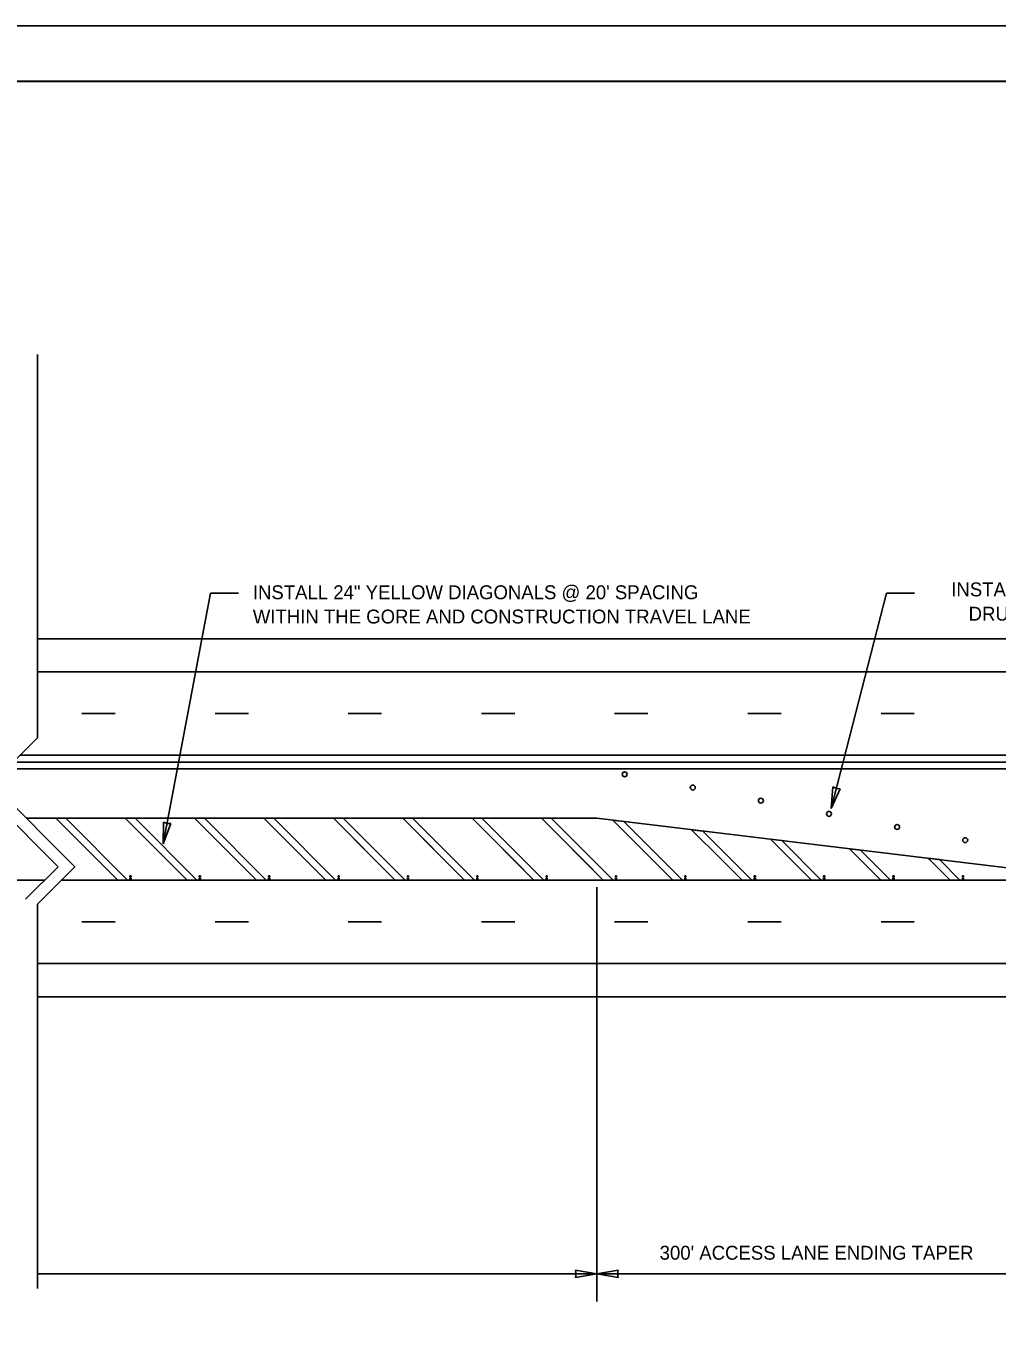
# Model space of a CAD drawing. Extents: x -2433 to -1135, y -5611 to -4633.
# Drawn here: x -1803.5 to -1523.6, y -5006.7 to -4632.8 of the extents above; entities that cross this region are included whole.
import ezdxf

# ---------------------------------------------------------------- set-up
doc = ezdxf.new("R2010")
doc.units = 0
for name, color, linetype in [('Level 42', 7, 'Continuous'), ('Level 45', 7, 'Continuous'), ('Level 46', 7, 'Continuous'), ('Level 48', 7, 'Continuous'), ('Level 49', 7, 'Continuous'), ('Level 50', 7, 'Continuous'), ('TR_WZ_TC_Edge Lines', 7, 'Continuous')]:
    doc.layers.add(name, color=color, linetype=linetype)

msp = doc.modelspace()

# ---------------------------------------------------------------- linework, layer by layer
at = {"layer": 'Level 42'}
msp.add_line((-1170.57, -4648.81), (-2364.77, -4648.78), dxfattribs=at)
msp.add_lwpolyline([(-2364.77, -4648.78), (-1304.73, -4648.78), (-1304.73, -5430.02), (-2364.77, -5430.02)], close=True, dxfattribs=at)
at = {"layer": 'Level 45'}
for p, q in [((-1805.25, -4843.04), (-1332.46, -4843.04)), ((-2323.46, -4879.04), (-1798.16, -4879.04)), ((-1793.36, -4879.04), (-1332.46, -4879.04)), ((-1773.56, -4878.08), (-1773.56, -4877.76)), ((-1773.56, -4877.76), (-1773.24, -4877.76)), ((-1773.24, -4878.08), (-1773.56, -4878.08)), ((-1773.56, -4878.72), (-1773.56, -4878.4)), ((-1773.56, -4878.4), (-1773.24, -4878.4)), ((-1773.24, -4878.72), (-1773.56, -4878.72)), ((-1773.24, -4877.76), (-1773.24, -4878.08)), ((-1773.24, -4878.4), (-1773.24, -4878.72)), ((-1753.56, -4878.08), (-1753.56, -4877.76)), ((-1753.56, -4877.76), (-1753.24, -4877.76)), ((-1753.24, -4878.08), (-1753.56, -4878.08)), ((-1753.56, -4878.72), (-1753.56, -4878.4)), ((-1753.56, -4878.4), (-1753.24, -4878.4)), ((-1753.24, -4878.72), (-1753.56, -4878.72)), ((-1753.24, -4877.76), (-1753.24, -4878.08)), ((-1753.24, -4878.4), (-1753.24, -4878.72)), ((-1733.56, -4878.08), (-1733.56, -4877.76)), ((-1733.56, -4877.76), (-1733.24, -4877.76)), ((-1733.24, -4878.08), (-1733.56, -4878.08)), ((-1733.56, -4878.72), (-1733.56, -4878.4)), ((-1733.56, -4878.4), (-1733.24, -4878.4)), ((-1733.24, -4878.72), (-1733.56, -4878.72)), ((-1733.24, -4877.76), (-1733.24, -4878.08)), ((-1733.24, -4878.4), (-1733.24, -4878.72)), ((-1713.56, -4878.08), (-1713.56, -4877.76)), ((-1713.56, -4877.76), (-1713.24, -4877.76)), ((-1713.24, -4878.08), (-1713.56, -4878.08)), ((-1713.56, -4878.72), (-1713.56, -4878.4)), ((-1713.56, -4878.4), (-1713.24, -4878.4)), ((-1713.24, -4878.72), (-1713.56, -4878.72)), ((-1713.24, -4877.76), (-1713.24, -4878.08)), ((-1713.24, -4878.4), (-1713.24, -4878.72)), ((-1693.56, -4878.08), (-1693.56, -4877.76)), ((-1693.56, -4877.76), (-1693.24, -4877.76)), ((-1693.24, -4878.08), (-1693.56, -4878.08)), ((-1693.56, -4878.72), (-1693.56, -4878.4)), ((-1693.56, -4878.4), (-1693.24, -4878.4)), ((-1693.24, -4878.72), (-1693.56, -4878.72)), ((-1693.24, -4877.76), (-1693.24, -4878.08)), ((-1693.24, -4878.4), (-1693.24, -4878.72)), ((-1673.56, -4878.08), (-1673.56, -4877.76)), ((-1673.56, -4877.76), (-1673.24, -4877.76)), ((-1673.24, -4878.08), (-1673.56, -4878.08)), ((-1673.56, -4878.72), (-1673.56, -4878.4)), ((-1673.56, -4878.4), (-1673.24, -4878.4)), ((-1673.24, -4878.72), (-1673.56, -4878.72)), ((-1673.24, -4877.76), (-1673.24, -4878.08)), ((-1673.24, -4878.4), (-1673.24, -4878.72)), ((-1653.56, -4878.08), (-1653.56, -4877.76)), ((-1653.56, -4877.76), (-1653.24, -4877.76)), ((-1653.24, -4878.08), (-1653.56, -4878.08)), ((-1653.56, -4878.72), (-1653.56, -4878.4)), ((-1653.56, -4878.4), (-1653.24, -4878.4)), ((-1653.24, -4878.72), (-1653.56, -4878.72)), ((-1653.24, -4877.76), (-1653.24, -4878.08)), ((-1653.24, -4878.4), (-1653.24, -4878.72)), ((-1633.56, -4878.08), (-1633.56, -4877.76)), ((-1633.56, -4877.76), (-1633.24, -4877.76)), ((-1633.24, -4878.08), (-1633.56, -4878.08)), ((-1633.56, -4878.72), (-1633.56, -4878.4)), ((-1633.56, -4878.4), (-1633.24, -4878.4)), ((-1633.24, -4878.72), (-1633.56, -4878.72)), ((-1633.24, -4877.76), (-1633.24, -4878.08)), ((-1633.24, -4878.4), (-1633.24, -4878.72)), ((-1613.56, -4878.08), (-1613.56, -4877.76)), ((-1613.56, -4877.76), (-1613.24, -4877.76)), ((-1613.24, -4878.08), (-1613.56, -4878.08)), ((-1613.56, -4878.72), (-1613.56, -4878.4)), ((-1613.56, -4878.4), (-1613.24, -4878.4)), ((-1613.24, -4878.72), (-1613.56, -4878.72)), ((-1613.24, -4877.76), (-1613.24, -4878.08)), ((-1613.24, -4878.4), (-1613.24, -4878.72)), ((-1593.56, -4878.08), (-1593.56, -4877.76)), ((-1593.56, -4877.76), (-1593.24, -4877.76)), ((-1593.24, -4878.08), (-1593.56, -4878.08)), ((-1593.56, -4878.72), (-1593.56, -4878.4)), ((-1593.56, -4878.4), (-1593.24, -4878.4)), ((-1593.24, -4878.72), (-1593.56, -4878.72)), ((-1593.24, -4877.76), (-1593.24, -4878.08)), ((-1593.24, -4878.4), (-1593.24, -4878.72)), ((-1573.56, -4878.08), (-1573.56, -4877.76)), ((-1573.56, -4877.76), (-1573.24, -4877.76)), ((-1573.24, -4878.08), (-1573.56, -4878.08)), ((-1573.56, -4878.72), (-1573.56, -4878.4)), ((-1573.56, -4878.4), (-1573.24, -4878.4)), ((-1573.24, -4878.72), (-1573.56, -4878.72)), ((-1573.24, -4877.76), (-1573.24, -4878.08)), ((-1573.24, -4878.4), (-1573.24, -4878.72)), ((-1553.56, -4878.08), (-1553.56, -4877.76)), ((-1553.56, -4877.76), (-1553.24, -4877.76)), ((-1553.24, -4878.08), (-1553.56, -4878.08)), ((-1553.56, -4878.72), (-1553.56, -4878.4)), ((-1553.56, -4878.4), (-1553.24, -4878.4)), ((-1553.24, -4878.72), (-1553.56, -4878.72)), ((-1553.24, -4877.76), (-1553.24, -4878.08)), ((-1553.24, -4878.4), (-1553.24, -4878.72)), ((-1533.56, -4878.08), (-1533.56, -4877.76)), ((-1533.56, -4877.76), (-1533.24, -4877.76)), ((-1533.24, -4878.08), (-1533.56, -4878.08)), ((-1533.56, -4878.72), (-1533.56, -4878.4)), ((-1533.56, -4878.4), (-1533.24, -4878.4)), ((-1533.24, -4878.72), (-1533.56, -4878.72)), ((-1533.24, -4877.76), (-1533.24, -4878.08)), ((-1533.24, -4878.4), (-1533.24, -4878.72))]:
    msp.add_line(p, q, dxfattribs=at)
at = {"layer": 'Level 46'}
for p, q in [((-1750.28, -4796.31), (-1763.96, -4868.57)), ((-1742.28, -4796.31), (-1750.28, -4796.31)), ((-1555.4, -4796.31), (-1571.36, -4858.37)), ((-1547.4, -4796.31), (-1555.4, -4796.31)), ((-1800.24, -4809.44), (-1332.46, -4809.44)), ((-1800.24, -4819.04), (-1332.46, -4819.04)), ((-1787.41, -4831.04), (-1777.81, -4831.04)), ((-1749.01, -4831.04), (-1739.41, -4831.04)), ((-1710.61, -4831.04), (-1701.01, -4831.04)), ((-1672.21, -4831.04), (-1662.61, -4831.04)), ((-1633.81, -4831.04), (-1624.21, -4831.04)), ((-1595.41, -4831.04), (-1585.81, -4831.04)), ((-1557.01, -4831.04), (-1547.41, -4831.04)), ((-1638.94, -4881.06), (-1638.94, -5000.52)), ((-1787.41, -4891.04), (-1777.81, -4891.04)), ((-1749.01, -4891.04), (-1739.41, -4891.04)), ((-1710.61, -4891.04), (-1701.01, -4891.04)), ((-1672.21, -4891.04), (-1662.61, -4891.04)), ((-1633.81, -4891.04), (-1624.21, -4891.04)), ((-1595.41, -4891.04), (-1585.81, -4891.04)), ((-1557.01, -4891.04), (-1547.41, -4891.04)), ((-1800.24, -4903.04), (-1332.46, -4903.04)), ((-1800.24, -4912.64), (-1332.46, -4912.64)), ((-1800.24, -4992.52), (-1491.33, -4992.52))]:
    msp.add_line(p, q, dxfattribs=at)
at = {"layer": 'Level 48'}
for p, q in [((-1807.25, -4845.04), (-1493.44, -4845.04)), ((-1494.3, -4846.96), (-1809.17, -4846.96))]:
    msp.add_line(p, q, dxfattribs=at)
at = {"layer": 'Level 49'}
for p, q in [((-1571.36, -4858.37), (-1570.88, -4852.15)), ((-1568.78, -4852.69), (-1571.36, -4858.37)), ((-1570.88, -4852.15), (-1569.88, -4852.6)), ((-1569.88, -4852.6), (-1568.78, -4852.69)), ((-1763.96, -4868.57), (-1763.88, -4862.33)), ((-1761.75, -4862.73), (-1763.96, -4868.57)), ((-1763.88, -4862.33), (-1762.85, -4862.72)), ((-1762.85, -4862.72), (-1761.75, -4862.73)), ((-1638.94, -4992.52), (-1645.09, -4991.43)), ((-1645.09, -4991.43), (-1644.9, -4992.52)), ((-1632.8, -4991.43), (-1638.94, -4992.52)), ((-1632.99, -4992.52), (-1632.8, -4991.43)), ((-1644.9, -4992.52), (-1645.09, -4993.6)), ((-1645.09, -4993.6), (-1638.94, -4992.52)), ((-1638.94, -4992.52), (-1632.8, -4993.6)), ((-1632.8, -4993.6), (-1632.99, -4992.52))]:
    msp.add_line(p, q, dxfattribs=at)
at = {"layer": 'Level 50'}
for p, q in [((-1800.24, -4838.04), (-1800.24, -4727.54)), ((-1813.42, -4851.21), (-1800.24, -4838.04)), ((-1794.28, -4875.16), (-1818.23, -4851.21)), ((-1789.47, -4875.16), (-1813.42, -4851.21)), ((-1803.64, -4884.52), (-1794.28, -4875.16)), ((-1800.24, -4885.93), (-1789.47, -4875.16)), ((-1800.24, -4885.93), (-1800.24, -4996.72))]:
    msp.add_line(p, q, dxfattribs=at)
msp.add_lwpolyline([(-2432.94, -4632.82), (-1157.59, -4632.82), (-1157.59, -5447.91), (-2432.94, -5447.91)], close=True, dxfattribs=at)
for centre in [(-1630.92, -4848.54), (-1611.28, -4852.34), (-1591.65, -4856.13), (-1572.01, -4859.93), (-1552.37, -4863.72), (-1532.74, -4867.52)]:
    msp.add_circle(centre, 0.72, dxfattribs=at)
at = {"layer": 'TR_WZ_TC_Edge Lines'}
for p, q in [((-1803.43, -4861.2), (-1638.94, -4861.2)), ((-1777.07, -4879.04), (-1794.91, -4861.2)), ((-1792.08, -4861.2), (-1794.91, -4861.2)), ((-1774.24, -4879.04), (-1792.08, -4861.2)), ((-1774.24, -4879.04), (-1792.08, -4861.2)), ((-1757.07, -4879.04), (-1774.91, -4861.2)), ((-1772.08, -4861.2), (-1774.91, -4861.2)), ((-1754.24, -4879.04), (-1772.08, -4861.2)), ((-1754.24, -4879.04), (-1772.08, -4861.2)), ((-1737.07, -4879.04), (-1754.91, -4861.2)), ((-1752.08, -4861.2), (-1754.91, -4861.2)), ((-1734.24, -4879.04), (-1752.08, -4861.2)), ((-1734.24, -4879.04), (-1752.08, -4861.2)), ((-1717.07, -4879.04), (-1734.91, -4861.2)), ((-1732.08, -4861.2), (-1734.91, -4861.2)), ((-1714.24, -4879.04), (-1732.08, -4861.2)), ((-1714.24, -4879.04), (-1732.08, -4861.2)), ((-1697.07, -4879.04), (-1714.91, -4861.2)), ((-1712.08, -4861.2), (-1714.91, -4861.2)), ((-1694.24, -4879.04), (-1712.08, -4861.2)), ((-1694.24, -4879.04), (-1712.08, -4861.2)), ((-1677.07, -4879.04), (-1694.91, -4861.2)), ((-1692.08, -4861.2), (-1694.91, -4861.2)), ((-1674.24, -4879.04), (-1692.08, -4861.2)), ((-1674.24, -4879.04), (-1692.08, -4861.2)), ((-1657.07, -4879.04), (-1674.91, -4861.2)), ((-1672.08, -4861.2), (-1674.91, -4861.2)), ((-1654.24, -4879.04), (-1672.08, -4861.2)), ((-1654.24, -4879.04), (-1672.08, -4861.2)), ((-1637.07, -4879.04), (-1654.91, -4861.2)), ((-1652.08, -4861.2), (-1654.91, -4861.2)), ((-1634.24, -4879.04), (-1652.08, -4861.2)), ((-1634.24, -4879.04), (-1652.08, -4861.2)), ((-1638.94, -4861.2), (-1491.33, -4879.04)), ((-1631.14, -4862.15), (-1634.35, -4861.76)), ((-1614.24, -4879.04), (-1631.14, -4862.15)), ((-1608.39, -4864.89), (-1611.61, -4864.51)), ((-1594.24, -4879.04), (-1608.39, -4864.89)), ((-1585.64, -4867.64), (-1588.86, -4867.26)), ((-1574.24, -4879.04), (-1585.64, -4867.64)), ((-1562.89, -4870.39), (-1566.11, -4870)), ((-1554.24, -4879.04), (-1562.89, -4870.39)), ((-1540.14, -4873.14), (-1543.36, -4872.75)), ((-1534.24, -4879.04), (-1540.14, -4873.14)), ((-1777.07, -4879.04), (-1774.24, -4879.04)), ((-1757.07, -4879.04), (-1754.24, -4879.04)), ((-1737.07, -4879.04), (-1734.24, -4879.04)), ((-1717.07, -4879.04), (-1714.24, -4879.04)), ((-1697.07, -4879.04), (-1694.24, -4879.04)), ((-1677.07, -4879.04), (-1674.24, -4879.04)), ((-1657.07, -4879.04), (-1654.24, -4879.04)), ((-1637.07, -4879.04), (-1634.24, -4879.04)), ((-1617.07, -4879.04), (-1614.24, -4879.04)), ((-1597.07, -4879.04), (-1594.24, -4879.04)), ((-1577.07, -4879.04), (-1574.24, -4879.04)), ((-1557.07, -4879.04), (-1554.24, -4879.04)), ((-1537.07, -4879.04), (-1534.24, -4879.04))]:
    msp.add_line(p, q, dxfattribs=at)
for points in [[(-1794.91, -4861.2), (-1782.91, -4873.2), (-1777.07, -4879.04)], [(-1774.91, -4861.2), (-1762.91, -4873.2), (-1757.07, -4879.04)], [(-1754.91, -4861.2), (-1742.91, -4873.2), (-1737.07, -4879.04)], [(-1734.91, -4861.2), (-1722.91, -4873.2), (-1717.07, -4879.04)], [(-1714.91, -4861.2), (-1702.91, -4873.2), (-1697.07, -4879.04)], [(-1694.91, -4861.2), (-1682.91, -4873.2), (-1677.07, -4879.04)], [(-1674.91, -4861.2), (-1662.91, -4873.2), (-1657.07, -4879.04)], [(-1654.91, -4861.2), (-1642.91, -4873.2), (-1637.07, -4879.04)], [(-1634.35, -4861.76), (-1622.91, -4873.2), (-1617.07, -4879.04)], [(-1611.61, -4864.51), (-1602.91, -4873.2), (-1597.07, -4879.04)], [(-1588.86, -4867.26), (-1582.91, -4873.2), (-1577.07, -4879.04)], [(-1566.11, -4870), (-1562.91, -4873.2), (-1557.07, -4879.04)], [(-1543.36, -4872.75), (-1542.91, -4873.2), (-1537.07, -4879.04)]]:
    msp.add_lwpolyline(points, dxfattribs=at)

# ---------------------------------------------------------------- texts
at = {"layer": 'Level 42'}
for s, p in [('INSTALL PORTABLE PLASTIC', (-1536.76, -4797.24)), ('INSTALL 24" YELLOW DIAGONALS @ 20\' SPACING', (-1738.12, -4798.06)), ("DRUMS @ 20'  INTERVALS", (-1531.75, -4804.24)), ('WITHIN THE GORE AND CONSTRUCTION TRAVEL LANE', (-1738.12, -4805.06)), ("300' ACCESS LANE ENDING TAPER", (-1620.83, -4988.45))]:
    msp.add_text(s, height=4, dxfattribs=at).set_placement(p)

doc.saveas('drawing.dxf')
